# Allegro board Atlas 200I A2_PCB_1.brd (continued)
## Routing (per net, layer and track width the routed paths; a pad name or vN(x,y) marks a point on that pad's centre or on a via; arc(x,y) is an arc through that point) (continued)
$51N189030: length 32.9
  TOP w0.203: v1(83.96,69.22) 83.96,69.74 84.12,69.9 84.12,70.02 85.17,71.06 85.17,75.24 84.91,75.49 84.91,82.69 83.87,83.73 U25.3 ; R625.2 v1(96.57,62.51)
  ART04 w0.203: v1(83.96,69.22) 83.96,68.69 86.31,66.34 92.95,66.34 96.57,62.73 v1(96.57,62.51)
$51N189031: length 14.2
  TOP w0.203: U25.2 v1(81.68,83.08) ; R627.2 71.01,80.45 v1(71.02,80.46)
  ART04 w0.203: v1(81.68,83.08) 81.59,83.16 78.78,83.16 78.54,82.92 78.14,82.92 77.9,83.16 75.84,83.16 74.79,82.1 74.79,81.6 73.65,80.46 v1(71.02,80.46)
$51N193077: length 2.1
  TOP w0.203: R678.2 119.25,69.79 118.75,70.29 U21.2
$51N193392: length 2.2
  TOP w0.203: R676.2 120.11,69.8 119.4,70.5 U21.3
$51N193887: length 1.7
  TOP w0.203: R553.1 122,79.18 U21.8
$51N194066: length 1.7
  TOP w0.203: R629.1 116.3,79.18 U33.8
$51N194833: length 2.4
  TOP w0.203: U21.4 120.05,70.72 121.11,69.66 R5.2
$51N194878: length 12.3
  TOP w0.203: U21.5 120.7,72.64 119.23,74.11 111.75,74.11 110.76,73.13 R6.2
$51N196011: length 2.1
  TOP w0.203: R612.2 113.7,70.16 U33.3
$51N196013: length 1.9
  TOP w0.203: U33.2 113.05,69.7 R671.2
$51N196656: length 3
  TOP w0.203: U33.5 115,70.62 115.35,70.27 116.22,70.27 116.42,70.06 R19.2
$51N196657: length 2.3
  TOP w0.203: R7.2 114.35,70.62 U33.4
$51N198291: length 1.9
  TOP w0.203: R634.2 113.05,81.37 U34.2
$51N198558: length 2.1
  TOP w0.203: U34.3 113.7,81.83 R620.2
$51N199282: length 2.3
  TOP w0.203: U34.4 114.35,82.29 R670.2
$51N199818: length 3
  TOP w0.203: U34.5 115,82.29 115.36,81.93 116.22,81.93 116.42,81.73 R641.2
$51N202756: length 8.5
  TOP w0.203: U34.8 116.3,90.52 115.66,91.17 113.9,91.17 113.25,90.52 112.14,90.52 R239.1
$51N202938: length 2.7
  TOP w0.203: U35.8 122.01,88.29 122.27,88.03 R552.1
$51N203980: length 1.9
  TOP w0.203: U35.2 118.76,81.37 R53.2
$51N204476: length 2.1
  TOP w0.203: U35.3 119.41,81.83 R557.2
$51N204970: length 2.4
  TOP w0.203: R572.2 120.83,81.32 120.06,82.1 U35.4
$51N205764: length 3
  TOP w0.203: R556.2 122.13,81.73 121.93,81.93 121.09,81.93 120.71,82.32 U35.5
$51N207141: length 4.2
  TOP w0.203: R20.1 74.21,87.59 75.47,86.33 U25.8
$52N827: length 1.4
  TOP w0.203: R482.1 v1(114.18,102.36) 114.21,102.36 114.46,102.61 U17.6
$52N828: length 1.4
  TOP w0.203: R481.1 v1(114.18,103.38) 114.45,103.11 U17.5
$52N832: length 4.3
  TOP w0.203: 121.03,101.35 121.03,101.07 120.78,100.81 119.13,100.81 118.87,101.07 R487.1 118.62,101.35 118.35,101.61 U17.1
$52N833: length 4.3
  TOP w0.203: U17.2 118.34,102.11 118.59,102.36 R486.1 118.87,102.08 119.1,101.85 120.8,101.85 121.03,102.08 121.03,102.36
$52N834: length 4.5
  TOP w0.203: U17.3 118.11,102.61 R488.1 118.87,103.1 119.1,102.87 120.8,102.87 121.03,103.1 121.03,103.38
$52N843: length 4.9
  TOP w0.203: R489.2 98.65,115.93 98.42,115.7 95.94,115.7 95.32,116.31 U18.5
$52N844: length 2.1
  TOP w0.203: R492.1 96,116.35 v1(95.76,116.59) 95.38,116.96 U18.6
$52N845: length 2
  TOP w0.203: U18.7 95.5,117.61 v1(95.76,117.35) 95.77,117.36 R493.1
$52N846: length 4
  TOP w0.203: v1(91.69,117.35) 91.43,117.61 U18.2 88.98,117.61 88.23,116.85 R490.2
$52N847: length 5.7
  TOP w0.203: R491.2 88.62,115.96 88.82,116.17 88.82,116.74 89.05,116.96 U18.3 91.12,116.96 91.31,116.76 92.25,116.76 v1(92.84,117.35)
$52N2706: length 10.4
  TOP w0.203: R498.1 117.04,100.46 117.04,94.34 v1(116.24,93.53) 115.44,92.74 U19.23
$52N2707: length 9.3
  TOP w0.203: R499.1 116.31,100.38 v1(116.31,94.51) 115.18,93.39 U19.22
$55N3286: length 2.3
  TOP w0.203: U36.1 91.28,75.81 90.51,75.04 90.51,74.92 R459.2
$55N3381: length 2.2
  TOP w0.203: Q1.3 75.31,95.71 75.11,95.91 R549.1 C307.1
$55N3383: length 3.8
  TOP w0.203: U36.40 98.55,85.04 98.79,85.28 R550.2
$55N3386: length 10.9
  TOP w0.203: v1(65.53,94.01) R560.1 65.53,92.41 R558.2 ; v1(69.95,90.09) 70.13,89.92 C317.1 70.27,89.43 70.82,89.97 X3.1
  ART03 w0.203: v1(65.53,94.01) 66.47,94.01 69.95,90.53 v1(69.95,90.09)
$55N3387: length 4.1
  TOP w0.203: X3.3 67.98,92.86 C314.1 66.98,93.29 R560.2 66.34,92.41 R559.2
$55N29278: length 2.9
  TOP w0.203: Q6.3 105.69,87.53 106.07,87.91 R555.1 C312.1
$55N30280: length 8.1
  TOP w0.203: U36.41 98.15,84.1 98.3,83.95 99.06,83.95 99.64,84.53 104.47,84.53 104.93,84.07 R458.2
$55N32703: length 7.8
  TOP w0.203: v1(99.07,79.83) 99.08,79.82 U36.28 100.19,79.82 100.51,80.14 R649.2 ; U36.16 v1(97.75,75.15)
  ART03 w0.203: v1(97.75,75.15) 99.07,76.47 v1(99.07,79.83)
$56N3501: length 2.7
  TOP w0.203: U37.2 26.77,115.67 27.43,116.33 27.43,116.61 R562.2
$56N3504: length 2.4
  TOP w0.203: R607.2 27.98,118.24 26.68,116.94 U37.3
$56N3505: length 2.1
  TOP w0.203: U37.6 17.58,116.94 R561.1
$56N3511: length 3.2
  TOP w0.203: U37.1 27.25,114.4 28.04,115.19 R563.1
$56N3513: length 2
  TOP w0.203: U37.5 17.33,118.21 R567.2
$56N3514: length 2.2
  TOP w0.203: U37.7 17.84,115.67 R619.2
$56N3541: length 2.1
  TOP w0.203: R570.1 83.47,93.68 83.91,94.12 U38.57
$56N3566: length 2.1
  TOP w0.203: U38.23 90.69,103.84 91.03,104.19 R573.2
$56N3571: length 0.9
  TOP w0.203: R570.2 R574.1
$56N3579: length 6.8
  TOP w0.203: C343.1 85.47,89.56 85.15,89.88 X4.1 84.75,90.13 83.69,91.19 81.84,91.19 81.69,91.34 R578.1 81.69,92.66 81.75,92.73 R580.2
$56N3581: length 6.1
  TOP w0.203: R579.2 80.9,92.58 80.87,92.56 R578.2 80.87,88.95 81.08,88.75 C344.1 81.56,88.75 81.88,88.43 X4.3
$56N19655: length 1.2
  TOP w0.203: U38.27 89.09,103.09 89.38,103.38 R651.2
$56N19722: length 1.1
  TOP w0.203: R652.1 82.92,100.97 U38.41

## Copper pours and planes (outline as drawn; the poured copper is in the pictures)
3V3_USB30_SW on ART03 (solid shape): 108.57,16.23 111.56,16.23 111.82,15.96 111.82,15.24 111.54,14.96 106.45,14.96 106.1,14.61 103.76,14.61 103.71,14.66 103.71,15.25 103.72,15.29 103.74,15.33 103.8,15.33 103.85,15.34 103.9,15.35 103.94,15.37 104.14,15.37 104.14,15.31 104.15,15.26 104.16,15.21 104.19,15.16 104.22,15.12 104.25,15.08 104.29,15.05 104.34,15.02 104.39,15 104.44,14.99 104.5,14.98 104.55,14.99 104.6,15 104.65,15.02 104.7,15.05 104.74,15.08 104.77,15.12 104.8,15.16 104.83,15.21 104.84,15.26 104.85,15.31 104.85,15.37 104.84,15.42 104.83,15.47 104.8,15.52 104.77,15.56 104.74,15.6 104.7,15.64 104.65,15.66 104.6,15.68 104.55,15.69 104.5,15.7 104.44,15.69 104.39,15.68 104.34,15.66 104.29,15.64 104.25,15.6 104.22,15.56 104.19,15.52 104.16,15.47 104.15,15.42 104.14,15.37 103.94,15.37 103.95,15.37 104,15.4 104.04,15.44 104.07,15.48 104.1,15.53 104.13,15.58 104.14,15.63 104.15,15.68 104.15,15.74 104.14,15.79 104.12,15.85 104.1,15.9 104.07,15.94 104.03,15.98 104.01,16 104.62,16.61 108.18,16.61
12V_FAN on TOP (solid shape): 117.66,111.95 117.66,110.25 117.52,110.1 117.5,110.1 117.5,107.91 117.09,107.5 115.3,107.5 115.04,107.77 115.04,107.91 115.66,107.91 115.66,108.18 115.29,108.18 115.29,107.91 115.04,107.91 115.04,108.8 115.06,108.8 115.06,109.57 115.61,109.57 115.61,109.83 115.06,109.83 115.06,110.06 115.61,110.06 115.61,110.34 115.06,110.34 115.06,110.57 115.61,110.57 115.61,110.83 115.06,110.83 115.06,111.07 115.61,111.07 115.61,111.33 115.06,111.33 115.06,111.99 115.33,112.25 117.36,112.25
AGND_AUDIO on TOP (solid shape): 102.75,53.76 102.76,53.67 102.82,53.58 103.22,53.18 103.22,53.17 103.24,53.08 103.28,53 103.28,51.96 103.28,51.93 103.28,51.43 102.9,51.05 102.84,50.95 102.81,50.85 102.81,50.45 102.84,50.34 102.9,50.25 102.97,50.18 102.97,49.74 102.45,49.74 102.4,49.7 102.4,47.88 102.37,47.85 102.14,47.85 102.1,47.89 102.1,49.7 102.06,49.74 101.03,49.74 101.03,49.91 101.04,49.93 101.09,50.02 101.11,50.13 101.06,50.32 100.92,50.45 100.89,50.46 100.89,54.28 100.97,54.28 100.98,54.27 101.09,54.2 101.22,54.18 101.47,54.28 101.58,54.53 101.57,54.6 101.55,54.67 101.56,54.77 101.64,54.81 102.75,54.81
AGND_AUDIO on TOP (solid shape): 102.51,47.43 102.53,47.4 103.16,46.78 103.16,46.76 103.29,46.58 103.5,46.51 103.76,46.61 103.86,46.86 103.79,47.08 103.6,47.21 103.59,47.21 103.48,47.32 103.45,47.44 103.55,47.5 104.11,47.5 104.24,47.37 104.24,46.28 104.01,46.05 100.43,46.05 100.3,46.18 100.3,46.63 100.47,46.8 100.49,46.83 100.51,46.86 100.57,46.88 100.61,46.84 100.72,46.6 100.97,46.51 101.16,46.56 101.29,46.71 101.29,46.72 101.34,46.77 101.42,46.8 101.49,46.76 101.53,46.71 101.66,46.56 101.85,46.51 102.11,46.61 102.21,46.86 102.18,47.01 102.08,47.14 102.08,47.5 102.47,47.5
AGND_AUDIO on TOP (solid shape): outline of 172 points within 128.7,34.73 134.34,42.21
AGND_MIC on TOP (solid shape): outline of 120 points within 129.18,35.72 130.98,37.53
GND on TOP (solid shape): 13.06,103.84 13.06,102.31 12.95,102.21 11.96,102.21 11.89,102.29 11.89,103.89 11.94,103.94 12.95,103.94
GND on TOP (solid shape): 17.25,60.91 17.25,57.35 16.94,57.05 15.21,57.05 14.94,57.33 14.94,61.19 15.19,61.44 16.71,61.44
GND on TOP (solid shape): 94.95,31.37 94.95,28.47 94.82,28.35 93.37,28.35 93.24,28.47 93.24,31.37 93.37,31.5 94.82,31.5
GND on TOP (solid shape): 112.17,26.42 112.17,25.23 112.09,25.16 110.25,25.16 110.11,25.3 110.11,26.21 110.54,26.64 111.94,26.64
GND on TOP (solid shape): 123.24,45.03 123.24,43.99 123.15,43.9 119.95,43.9 119.86,43.99 119.86,45.03 119.93,45.1 123.18,45.1
GND on TOP (solid shape): 8.92,15.11 8.9,15.1 8.9,14.44 8.64,14.17 6.43,14.17 5.99,14.61 5.99,16.2 6.07,16.28 8.92,16.28
GND on TOP (solid shape): 88.65,31.37 88.65,28.5 88.54,28.4 87.33,28.4 86.96,28.77 86.96,31.3 87.15,31.5 88.52,31.5
GND on TOP (solid shape): 125.76,22.4 125.76,19.41 125.55,19.2 121.44,19.2 120.12,17.88 118.34,17.88 118.31,17.91 118.31,18.59 118.57,18.85 118.57,22.07 119.23,22.73 125.43,22.73
GND on TOP (solid shape): 71.55,27.3 71.55,25.31 71.22,24.98 71.22,21.69 71.04,21.51 69.19,21.51 68.71,22 68.71,25.25 69.06,25.6 69.9,25.6 70.33,26.04 70.33,27.18 70.59,27.43 71.42,27.43
GND on TOP (solid shape): 101.83,36.8 101.83,35.31 101.22,34.7 101.22,30.86 100.84,30.48 100.03,30.48 99.77,30.73 99.77,32.77 99.06,33.48 99.06,35.92 99.35,36.21 99.35,36.89 99.49,37.03 101.6,37.03
GND on TOP (solid shape): 122.81,111.91 122.81,109.73 123.09,109.45 123.67,109.45 123.77,109.35 123.77,107.87 123.65,107.75 122.99,107.75 122.76,107.98 122.05,107.98 121.95,108.08 121.95,111.94 122.15,112.14 122.58,112.14
GND on TOP (solid shape): 36.68,118.31 36.68,117.47 36.47,117.27 33.05,117.27 32.89,117.42 32.89,117.58 33.58,117.58 33.58,117.96 33.25,117.96 33.25,117.58 32.89,117.58 32.89,118.39 33.07,118.57 36.42,118.57
GND on TOP (solid shape): 2.83,50.2 2.93,50.14 3.05,50.11 3.96,50.11 4.01,50.06 4.01,48.67 3.94,48.59 0.91,48.59 0.53,48.97 0.53,50.47 0.76,50.7 2.34,50.7
GND on TOP (solid shape): 1,18.53 4.52,18.53 4.52,17.5 4.22,17.2 3.23,17.2 2.76,16.73 2.76,15.1 2.62,14.96 1.42,14.96 1.07,14.61 0.64,14.61 0.51,14.73 0.51,18.9 0.81,19.2 1,19.2
GND on TOP (solid shape): 4.29,90.35 4.29,89.61 3,88.32 3,87.27 2.31,86.59 0.81,86.59 0.56,86.84 0.56,90.3 0.62,90.36 1.91,90.36 1.91,89.76 2.71,89.76 2.71,90.36 3.38,90.36 3.38,90.91 3.73,90.91
GND on TOP (solid shape): 46.51,119.2 46.51,118.01 46.28,117.78 43.21,117.78 42.93,118.06 42.93,118.36 42.98,118.54 42.93,118.73 42.93,119.33 43.09,119.49 46.22,119.49
GND on TOP (solid shape): 6.17,54.76 6.17,53.36 6.13,53.33 5.93,53.13 5.52,53.13 5.28,53.37 5.28,53.59 5.22,53.65 5.17,53.7 4.84,53.7 4.77,53.77 4.77,54.79 4.79,54.81 6.12,54.81
GND on TOP (solid shape): 24.21,79.78 24.21,79.12 24.51,78.82 24.51,77.09 24.26,76.83 22.38,76.83 22.38,77.14 22.05,77.14 22.05,77.39 22.67,77.39 22.67,79.1 22.3,79.1 22.3,77.39 22.05,77.39 22.05,79.45 22.45,79.86 24.13,79.86
GND on TOP (solid shape): 55.68,13.79 55.68,2.01 54.74,1.07 54.31,1.07 54.12,1.12 53.94,1.07 53.34,1.07 53.09,1.32 53.09,11.53 52.5,12.12 50.75,12.12 50.11,12.75 50.11,14.12 50.44,14.45 55.02,14.45
GND on TOP (solid shape): 80.88,22.8 81.05,22.8 81.28,22.56 81.28,22.35 81.1,22.17 79.76,22.17 79.53,21.95 79.53,21.59 79.38,21.44 78.89,21.44 78.77,21.56 78.77,22 78.64,22.12 78.64,22.76 78.71,22.83 79.73,22.83 79.89,22.99 80.69,22.99
GND on TOP (solid shape): 48.46,36.2 48.46,34.21 48.01,33.76 47.19,33.76 46.94,33.5 46.94,33.05 47.14,32.84 47.57,32.84 47.65,32.77 47.65,31.95 47.6,31.9 46,31.9 45.92,31.98 45.92,32.74 46,32.82 46.53,32.82 46.63,32.92 46.63,33.76 47.09,34.21 47.09,36.37 47.22,36.5 48.16,36.5
GND on TOP (solid shape): 59.59,21.64 59.59,19.66 59.13,19.2 58.31,19.2 58.06,18.96 58.06,18.49 58.27,18.29 58.7,18.29 58.78,18.21 58.78,17.4 58.72,17.35 57.12,17.35 57.05,17.42 57.05,18.19 57.12,18.26 57.66,18.26 57.76,18.36 57.76,19.2 58.22,19.66 58.22,21.82 58.34,21.95 59.28,21.95
GND on TOP (solid shape): 50.27,22.62 53.37,22.62 53.42,22.61 53.47,22.61 54.39,22.61 54.51,22.62 54.61,22.67 54.62,22.68 54.76,22.68 55.22,22.23 55.22,20.85 54.97,20.6 49.02,20.6 48.77,20.85 48.77,22.23 49.38,22.84 50.06,22.84
GND on TOP (solid shape): 66.95,27.46 66.95,26.11 66.83,25.98 66.09,25.98 65.91,26.16 66.57,26.16 66.57,26.47 66.22,26.47 66.22,26.16 65.91,26.16 65.63,26.44 65.63,27.08 66.6,27.08 66.6,27.36 66.22,27.36 66.22,27.08 65.63,27.08 65.63,27.41 65.91,27.69 66.73,27.69
GND on TOP (solid shape): 110.01,34.06 110.67,34.06 111.02,33.71 111.02,32.77 110.67,32.41 110.07,32.41 110.07,32.46 109.15,32.46 109.09,32.52 109.09,32.64 109.55,32.64 109.55,33.05 109.25,33.05 109.25,32.64 109.09,32.64 109.09,32.8 108.8,32.8 108.64,32.97 105.71,32.97 105.59,33.1 105.59,34.29 105.94,34.65 109.42,34.65
GND on TOP (solid shape): 25.08,54.14 25.07,54.12 25.07,48.82 24.84,48.59 22.24,48.59 21.97,48.72 21.7,48.59 21.54,48.59 20.85,49.28 20.85,51.46 21.97,52.58 21.97,53.85 22.33,54.2 25.02,54.2
GND on TOP (solid shape): 112.85,91.36 112.85,90.93 112.75,90.83 111.92,90.83 111.46,90.37 109.46,90.37 109.35,90.48 109.35,90.73 109.96,90.73 109.96,90.75 111.05,90.75 111.05,91.13 110.76,91.13 110.76,90.75 109.96,90.75 109.96,91.14 109.66,91.14 109.66,90.73 109.35,90.73 109.35,91.36 109.46,91.47 111.39,91.47 111.41,91.49 112.73,91.49
GND on TOP (solid shape): 9.91,67.21 9.91,65.86 9.8,65.76 9.19,65.76 9.17,65.74 8.96,65.74 8.96,65.76 8.09,65.76 8.09,65.74 7.92,65.74 7.8,65.86 7.8,66.11 7.81,66.13 7.83,66.19 7.85,66.24 8.69,66.24 8.69,66.6 8.36,66.6 8.36,66.24 7.85,66.24 7.85,66.29 7.85,66.35 7.83,66.4 7.81,66.45 7.8,66.48 7.8,67.18 8.05,67.44 9.68,67.44
GND on TOP (solid shape): 23.75,82.55 25.96,82.55 25.98,82.52 25.98,81.61 25.88,81.5 22.38,81.5 22.38,82.33 22.63,82.18 22.93,82.13 23.35,82.24 23.65,82.56 23.65,82.56 23.7,82.6
GND on TOP (solid shape): 74.12,22.07 74.12,21.77 74.6,21.29 74.6,20.23 74.31,19.93 74.04,19.93 73.63,19.52 73.6,19.52 73.6,18 73.5,17.89 73.09,17.89 73.06,17.92 73.06,18.58 73.01,18.58 73.01,18.97 73.07,19.1 73.09,19.25 73.09,19.57 73.49,19.97 73.49,21.11 73.28,21.11 73.28,21.95 73.51,22.17 74.02,22.17
GND on TOP (solid shape): 101.02,14.81 101.02,13.31 100.78,13.08 100.51,13.08 100.38,12.95 100.22,12.95 100.22,12.8 100.1,12.67 100.1,12.12 99.77,11.79 99.14,11.79 99.11,11.81 99.11,12.29 99.12,12.31 99.12,12.53 99.96,13.38 99.96,13.41 100.69,13.41 100.69,13.68 100.28,13.68 100.28,13.41 99.96,13.41 99.96,14.18 99.69,14.45 99.21,14.45 99.09,14.58 99.09,14.99 99.16,15.06 100.76,15.06
GND on TOP (solid shape): 59.11,42.49 59.11,41.27 58.85,41.02 58.85,40.31 58.83,40.29 58.83,39.11 58.55,39.11 58.55,38.84 58.39,38.84 58.29,38.94 58.29,39.62 58.67,39.62 58.67,40.03 58.42,40.03 58.42,39.62 58.29,39.62 58.29,40.56 58.7,40.56 58.7,40.94 58.45,40.94 58.45,40.56 58.29,40.56 58.29,41.36 58.42,41.49 58.42,42.49 58.52,42.6 59,42.6
GND on TOP (solid shape): 89.43,109.22 89.43,108.28 88.72,107.57 87.81,107.57 87.43,107.19 85.52,107.19 85.37,107.34 85.37,107.9 88.65,107.9 88.65,108.36 88.34,108.36 88.34,107.9 85.37,107.9 85.37,108.84 88.24,108.84 88.24,109.27 87.96,109.27 87.96,108.84 85.37,108.84 85.37,108.86 86.08,109.58 89.08,109.58
GND on TOP (solid shape): 101.45,19.18 101.45,17.88 101.12,17.55 100.25,17.55 99.85,17.14 99.39,17.14 99.31,17.22 99.31,17.5 99.72,17.5 99.72,17.87 100.86,17.87 100.86,18.31 100.56,18.31 100.56,17.87 99.72,17.87 99.72,17.93 99.44,17.93 99.44,17.5 99.31,17.5 99.31,18.54 100.1,18.54 100.1,18.8 99.69,18.8 99.69,18.54 99.31,18.54 99.31,19.28 99.57,19.53 101.09,19.53
GND on TOP (solid shape): 7.31,64.08 7.33,64.07 7.37,64.05 7.42,64.04 7.47,64.03 7.52,64.03 7.56,64.04 7.6,64.05 7.66,64.07 7.79,63.93 7.79,63.14 7.82,63.14 7.82,62.99 7.79,62.99 7.79,62.33 7.74,62.28 6.35,62.28 6.17,62.46 7.34,62.46 7.34,62.69 6.93,62.69 6.93,62.46 6.17,62.46 6.1,62.53 6.1,63.45 7.37,63.45 7.37,63.73 6.96,63.73 6.96,63.45 6.1,63.45 6.1,63.55 6.63,64.08
GND on TOP (solid shape): 55.52,44.73 55.52,43.84 55.8,43.56 57.02,43.56 57.1,43.48 57.1,42.95 57.07,42.93 54.84,42.93 54.69,43.08 56.74,43.08 56.74,43.36 56.31,43.36 56.31,43.08 54.69,43.08 54.66,43.1 55.8,43.1 55.8,43.36 55.4,43.36 55.4,43.1 54.66,43.1 54.66,43.23 55.12,43.23 55.12,43.66 54.84,43.66 54.84,43.23 54.66,43.23 54.66,43.33 54.46,43.54 54.39,43.54 54.24,43.69 54.24,44.84 54.33,44.93 55.32,44.93
GND on TOP (solid shape): 122.35,25.86 122.35,25.68 122.4,25.63 122.4,25.57 122.46,25.57 122.56,25.48 122.91,25.48 123.29,25.1 123.29,23.32 123.14,23.16 119.81,23.16 119.53,23.44 119.53,24.4 122.18,24.4 122.18,24.77 120.59,24.77 120.59,24.4 119.53,24.4 119.53,25.02 122.2,25.02 122.2,25.3 120.6,25.3 120.6,25.02 119.53,25.02 119.53,25.5 122.2,25.5 122.2,25.78 120.6,25.78 120.6,25.5 119.53,25.5 119.53,25.68 119.87,26.02 122.19,26.02
GND on TOP (solid shape): 60.27,92.43 60.27,91.77 59.95,91.45 59.85,91.4 59.65,91.29 59.46,91.19 59.28,91.07 59.1,90.95 58.92,90.82 58.75,90.68 58.58,90.54 58.42,90.4 58.34,90.32 56.26,90.32 56.08,90.5 56.08,90.58 56.13,90.58 56.13,91.39 56.44,91.69 57.78,91.69 57.86,91.77 58.93,91.77 58.93,91.87 59.94,91.87 59.94,92.35 59.64,92.35 59.64,91.87 58.93,91.87 58.93,92.25 58.65,92.25 58.65,91.77 57.86,91.77 58.62,92.53 60.17,92.53
GND on TOP (solid shape): 111.91,44.35 111.91,43.23 112.31,42.83 112.31,40.8 111.99,40.48 111.99,39.17 111.84,39.01 110.16,39.01 109.98,39.19 109.98,41.05 112.02,41.05 112.02,41.3 111.67,41.3 111.67,41.05 109.98,41.05 109.98,41.09 109.99,41.12 110,41.18 110.01,41.25 110.01,41.31 110,41.37 109.99,41.44 109.98,41.47 109.98,42.39 109.97,42.4 111.97,42.4 111.97,42.7 111.56,42.7 111.56,42.4 109.97,42.4 109.6,42.77 108.92,42.77 108.66,43.03 108.66,43.61 109.07,44.02 109.91,44.02 110.41,44.53 111.73,44.53
GND on TOP (solid shape): 95.55,37.31 95.55,35.13 95.22,34.8 90.8,34.8 90.19,35.41 90.18,35.42 90.11,35.48 89.17,35.48 89.07,35.38 89.07,34.65 89.02,34.59 87.04,34.59 87.01,34.62 87.01,35.36 86.89,35.48 86.1,35.48 86.05,35.53 86.05,35.69 86.1,35.74 86.89,35.74 86.99,35.84 86.99,36.6 87.04,36.65 89.1,36.65 89.17,36.58 89.17,35.84 89.27,35.74 90.11,35.74 90.18,35.81 90.19,35.82 90.82,36.45 91.29,36.45 91.29,36.91 91.03,36.91 91.03,36.45 90.82,36.45 90.82,37.03 90.96,37.16 91.81,37.16 92.04,37.39 95.47,37.39
GND on TOP (solid shape): 42.65,43.94 42.33,43.94 42.33,42.52 41.55,41.73 40.03,41.73 39.95,41.66 35.74,41.66 35.68,41.71 35.64,41.74 35.6,41.76 35.56,41.78 35.51,41.78 35.48,41.78 34.67,41.78 34.67,41.91 32.99,41.91 32.99,41.81 32.97,41.79 32.92,41.78 32.87,41.77 32.82,41.74 32.77,41.71 32.72,41.66 32.31,41.66 32.18,41.78 32.18,42.85 32.59,42.85 32.59,43.26 32.31,43.26 32.31,42.85 32.18,42.85 32.18,43.44 33.08,43.44 33.08,43.71 36.14,43.71 36.32,43.54 41.45,43.54 41.65,43.73 41.89,43.73 41.89,43.97 42.01,44.09 42.65,44.09
GND on TOP (solid shape): 2.05,103.4 2.26,103.34 2.47,103.4 3.73,103.4 3.94,103.34 4.15,103.4 5.71,103.4 5.92,103.34 6.13,103.4 7.49,103.4 7.7,103.34 7.91,103.4 7.92,103.4 8.13,103.2 8.13,102.48 7.98,102.33 7.98,102.18 7.87,102.08 0.91,102.08 0.58,102.41 0.58,103.23 0.76,103.4
GND on TOP (solid shape): 53.06,117.08 53.06,115.94 52.96,115.85 51.97,115.85 51.71,115.6 51.18,115.6 51,115.42 51,114.76 50.92,114.67 49.71,114.67 49.32,114.29 49.32,113.86 49.23,113.77 44.88,113.77 44.65,114 44.65,114.07 45.42,114.07 45.42,114.3 44.96,114.3 44.96,114.07 44.65,114.07 44.65,114.78 44.78,114.91 50.72,114.91 50.72,115.19 50.34,115.19 50.34,114.91 44.78,114.91 45.57,115.7 46.23,115.7 46.38,115.85 47.52,115.85 47.52,116.31 47.22,116.31 47.22,115.85 46.38,115.85 47.12,116.59 48.29,116.59 48.74,117.04 52.04,117.04 52.16,117.15 52.98,117.15
GND on TOP (solid shape): 106.55,107.95 106.55,106.43 103.38,103.25 101.22,103.25 100.46,102.49 100.46,98.61 100.43,98.58 100.43,95.98 100.33,95.89 100.33,95.25 98.93,95.25 98.81,95.38 98.81,97.28 98.73,97.36 98.73,100.31 98.6,100.44 98.6,100.79 98.7,100.79 98.7,101.04 99.59,101.04 99.59,101.35 99.11,101.35 99.11,101.04 98.7,101.04 98.7,101.65 98.6,101.65 98.6,101.96 98.73,102.08 98.73,102.39 99.47,102.39 99.47,102.64 99.03,102.64 99.03,102.39 98.73,102.39 98.73,103.4 99.39,103.4 99.39,103.68 99.01,103.68 99.01,103.4 98.73,103.4 98.73,104.39 99.36,104.39 99.36,104.65 98.98,104.65 98.98,104.39 98.73,104.39 98.73,105.84 99.95,107.06 100.01,107.11 100.12,107.19 100.22,107.28 100.32,107.38 100.41,107.48 100.49,107.59 100.54,107.65 102.11,109.22 105.28,109.22
GND on TOP (solid shape): 1.93,83.69 1.97,83.69 2,83.67 2.01,83.65 2.03,83.63 2.03,83.6 2.03,83.57 1.99,83.5 1.95,83.42 1.92,83.34 1.89,83.26 1.87,83.17 1.85,83.08 1.85,83 1.85,82.9 1.85,82.81 1.87,82.72 1.89,82.63 1.93,82.54 1.97,82.45 2.01,82.37 2.07,82.29 2.13,82.22 2.2,82.15 2.27,82.09 2.34,82.04 2.43,81.99 2.51,81.95 2.6,81.92 2.69,81.9 2.78,81.88 2.88,81.87 2.97,81.87 3.06,81.88 3.14,81.89 3.23,81.91 3.31,81.94 3.39,81.97 3.46,82.02 3.54,82.05 3.57,82.05 3.59,82.05 3.62,82.03 3.64,82.02 3.65,81.99 3.66,81.95 3.66,80.62 3.18,80.14 3.18,77.1 3.07,76.99 1.68,76.99 0.51,78.16 0.51,82.96 1.19,82.96 1.19,83.41 0.89,83.41 0.89,82.96 0.51,82.96 0.51,83.41 0.79,83.69
GND on TOP (solid shape): 31.65,45.62 31.65,45.29 31.57,45.21 31.57,41.53 32.15,40.95 32.15,40.21 32.31,40.06 33.13,40.06 33.32,39.86 33.32,37.54 32.71,36.93 31.36,36.93 30.94,37.36 30.94,39.37 32.98,39.37 32.98,39.76 32.69,39.76 32.69,39.37 30.94,39.37 30.94,39.52 31.75,39.52 31.75,39.88 31.29,39.88 31.29,39.52 30.94,39.52 30.94,40.51 31.75,40.51 31.75,40.79 31.27,40.79 31.27,40.51 30.94,40.51 30.94,41.12 31.39,41.12 31.39,41.51 31.11,41.51 31.11,41.12 30.94,41.12 30.94,42.06 31.39,42.06 31.39,42.42 31.17,42.42 31.17,42.06 30.94,42.06 30.94,42.98 31.39,42.98 31.39,43.38 31.14,43.38 31.14,42.98 30.94,42.98 30.94,43.92 31.39,43.92 31.39,44.35 31.14,44.35 31.14,43.92 30.94,43.92 30.94,44.91 31.42,44.91 31.42,45.42 31.17,45.42 31.17,44.91 30.94,44.91 30.94,45.62 31.04,45.72 31.55,45.72
GND on TOP (solid shape): 81.38,28.02 81.38,26.75 81.84,26.29 81.84,25.73 82.07,25.5 82.64,25.5 82.64,27.45 82.67,27.49 83,27.49 83.01,27.48 83.01,26.86 82.89,26.74 82.89,25.82 82.96,25.75 83.09,25.75 83.13,25.8 83.13,26.4 83.37,26.4 83.38,26.38 83.38,25.48 83.97,25.48 84.02,25.43 84.02,23.5 83.97,23.44 83.39,23.44 83.38,23.44 83.38,22.55 83.14,22.55 83.13,22.56 83.13,23.1 83.12,23.11 82.89,23.11 82.89,22.55 82.87,22.53 82.65,22.53 82.64,22.55 82.64,23.38 82.6,23.42 82.07,23.42 82.07,24.7 81.86,24.91 81.86,25.29 81.7,25.29 81.64,25.35 81.05,25.35 81.05,25.8 81,25.85 81,26.05 80.8,26.05 80.58,26.26 77.55,26.26 77.24,26.57 77.23,26.57 77.03,26.77 75.85,26.77 74.79,25.7 71.98,25.7 71.7,25.98 71.7,27.48 72.11,27.89 74.2,27.89 75.32,27.43 75.34,27.41 78.74,27.41 79.25,27.91 80.31,27.91 80.59,28.19 81.2,28.19
GND on TOP (solid shape): 10.32,43.65 10.38,43.63 10.43,43.62 10.49,43.62 10.54,43.63 10.6,43.65 10.63,43.66 11.64,43.66 11.66,43.65 11.71,43.62 11.77,43.6 11.83,43.59 11.91,43.59 12.12,43.38 12.12,39.52 11.91,39.32 11.48,39.32 11.23,39.57 11.23,39.83 11.71,39.83 11.71,40.28 11.46,40.28 11.46,39.83 11.23,39.83 11.23,41.05 11.73,41.05 11.73,41.45 11.46,41.45 11.46,41.05 11.23,41.05 11.23,42.29 11.05,42.47 11.05,42.49 11.02,42.49 10.97,42.55 8.2,42.55 7.9,42.24 7.9,39.52 7.75,39.37 6.68,39.37 6.6,39.45 6.6,39.67 7.52,39.67 7.52,39.98 7.16,39.98 7.16,39.67 6.6,39.67 6.6,40.79 7.52,40.79 7.52,41.1 7.16,41.1 7.16,40.79 6.6,40.79 6.6,42.95 10.74,42.95 10.74,43.36 10.49,43.36 10.49,42.95 9.78,42.95 9.78,43.38 9.47,43.38 9.47,42.95 8.79,42.95 8.79,43.38 8.51,43.38 8.51,42.95 6.6,42.95 6.6,43.03 7.24,43.66 10.29,43.66
GND on TOP (solid shape): 31.65,57.53 31.65,55.29 31.75,55.19 31.75,52.95 31.73,52.93 31.7,52.89 31.68,52.84 31.67,52.79 31.67,52.77 31.67,52.39 31.67,52.36 31.68,52.31 31.7,52.27 31.73,52.23 31.78,52.18 31.78,51.46 31.91,51.32 31.91,51.29 31.91,51.26 31.91,51.24 31.89,51.21 31.84,51.18 31.8,51.15 31.76,51.11 31.72,51.07 31.7,51.03 31.68,50.98 31.66,50.93 31.66,50.88 31.66,50.82 31.66,50.77 31.68,50.72 31.7,50.67 31.73,50.62 31.77,50.58 31.81,50.55 31.85,50.52 31.9,50.49 31.97,50.47 31.97,49.82 31.9,49.76 31.9,47.9 31.88,47.88 31.6,47.88 31.6,49.78 31.39,49.78 31.39,47.88 31.11,47.88 31.11,49.78 30.89,49.78 30.89,47.88 30.68,47.88 30.61,47.96 30.61,49.78 30.6,49.79 30.56,49.83 30.35,49.83 30.3,49.89 30.3,51 30.35,51.05 30.35,55.14 31.37,55.14 31.37,57.28 31.14,57.28 31.14,55.14 30.86,55.14 30.86,57.28 30.63,57.28 30.63,55.14 30.35,55.14 30.35,55.23 30.36,55.23 30.36,57.41 30.35,57.41 30.35,57.58 30.38,57.61 31.57,57.61
GND on TOP (solid shape): outline of 81 points within 1.78,50.72 6.45,57.25
GND on TOP (solid shape): outline of 98 points within 78.87,87.35 81.81,101.09
GND on TOP (solid shape): 111.48,19.1 111.48,17.67 111.32,17.51 110.63,17.51 110.54,17.61 110.54,18.18 110.54,18.21 110.36,18.64 109.93,18.81 109.72,18.77 109.54,18.66 109.52,18.65 109.42,18.65 109.4,18.66 109.22,18.77 109.01,18.81 108.76,18.76 108.55,18.6 108.48,18.53 108.48,18.51 108.48,18.5 108.42,18.36 108.41,18.21 108.41,18.16 108.42,18.1 108.42,17.6 108.34,17.52 107.91,17.52 107.79,17.63 107.79,18.18 107.79,18.21 107.62,18.64 107.19,18.81 106.98,18.77 106.79,18.66 106.78,18.65 106.68,18.65 106.66,18.66 106.48,18.77 106.26,18.81 105.84,18.64 105.66,18.21 105.67,18.16 105.67,18.1 105.67,17.58 105.63,17.53 105.04,17.53 104.86,17.71 104.86,18.83 104.86,18.83 104.86,19.04 105.03,19.2 111.38,19.2
GND on TOP (solid shape): outline of 126 points within 68.28,110.55 81.51,117.16
GND on TOP (solid shape): outline of 162 points within 48.59,29.68 54.58,36.07
GND on TOP (solid shape): outline of 216 points within 65.25,111.2 86.87,119.46
GND on BOTTOM (solid shape): 47.61,31.92 45.96,31.92 45.96,32.8 47.61,32.8
GND on BOTTOM (solid shape): 58.7,17.39 57.16,17.39 57.16,18.21 58.7,18.21
GND on BOTTOM (solid shape): 63.04,113.67 59.39,113.67 59.39,117.17 63.04,117.17
GND on BOTTOM (solid shape): 83.92,23.56 82.07,23.56 82.07,25.4 83.92,25.4
GND on BOTTOM (solid shape): 88.98,34.7 87.13,34.7 87.13,36.52 88.98,36.52
GND on BOTTOM (solid shape): 109.71,13.6 106.65,13.6 106.65,14.66 109.71,14.66
GND on BOTTOM (solid shape): 116.76,101.72 115.73,101.72 115.73,102.96 116.76,102.96
GND on BOTTOM (solid shape): 54.58,0.53 54.56,0.51 48.56,0.51 48.56,1.02 54.58,1.02
GND on BOTTOM (solid shape): 13.64,55.42 13.64,51.86 9.93,51.86 9.78,52.01 9.78,55.35 10.01,55.58 13.48,55.58
GND on BOTTOM (solid shape): 59.92,35.64 59.92,32.56 59.66,32.31 56.29,32.31 56.03,32.56 56.03,35.64 56.29,35.89 59.66,35.89
GND on ART03 (solid shape): 69.08,45.59 67.69,45.59 67.69,50.55 69.08,50.55
GND on ART03 (solid shape): 72.52,46.99 70.81,46.99 70.81,50.55 72.52,50.55
GND on ART03 (solid shape): 76.82,54.23 73.21,54.23 73.21,57.91 76.82,57.91
GND on ART03 (solid shape): 72.25,54.23 70.63,54.23 70.4,54.46 70.4,57.85 70.46,57.91 72.25,57.91
GND on ART03 (solid shape): 46.94,50.24 46.94,47.19 46.81,47.07 40.61,47.07 40.51,47.17 40.51,50.37 46.81,50.37
GND on ART03 (solid shape): 88.83,57.7 88.83,54.18 88.83,54.14 88.77,54.08 82.27,54.08 82.26,54.09 82.26,57.74 82.27,57.76 88.77,57.76
GND on ART03 (solid shape): 90.54,50.53 90.58,50.44 90.65,50.37 90.65,47.17 90.53,47.04 82.51,47.04 82.51,50.55 90.53,50.55
GND on ART03 (solid shape): 111.4,12.09 111.4,9.09 111.33,9.02 105.64,9.02 105.03,9.63 105.03,10.95 105.54,11.46 105.54,11.96 105.77,12.19 111.3,12.19
GND on ART03 (solid shape): 75.1,50.55 75.17,50.52 75.25,50.51 75.33,50.52 75.4,50.55 77.05,50.55 77.05,46.99 73.48,46.99 73.48,50.55
GND on ART03 (solid shape): 39.65,27.58 39.65,27.13 39.75,27.03 39.75,24.95 40.45,24.25 40.49,24.25 40.56,24.18 44.2,24.18 44.31,24.07 44.31,22.8 44.04,22.53 36.5,22.53 35.79,23.25 35.79,27.47 35.92,27.6 39.63,27.6
GND on ART03 (solid shape): 42.79,28.69 42.79,28.12 42.97,27.94 42.97,27.48 43.48,26.97 44.6,26.97 44.64,26.94 44.64,25.3 40.85,25.3 40.61,25.54 40.61,27.48 40.95,27.82 42.09,27.82 42.44,28.17 42.44,28.66 42.51,28.73 42.75,28.73
GND on ART03 (solid shape): 92.19,14.24 92.19,12.17 92.13,11.98 92.19,11.79 92.19,8.68 91.86,8.36 86.22,8.36 86.11,8.47 86.11,11.79 86.26,11.93 86.26,13.6 86.26,13.6 86.26,14.25 86.39,14.38 92.05,14.38
GND on ART03 (solid shape): 35.13,50.37 35.24,50.11 35.51,50 35.77,50.11 35.89,50.37 39.45,50.37 39.45,47.07 31.9,47.07 31.57,47.4 31.57,50.37
GND on ART03 (solid shape): 97.68,57.67 97.68,54.14 97.66,54.13 95.94,54.13 95.83,54.18 95.71,54.2 94.79,54.2 94.67,54.18 94.56,54.13 92.94,54.13 92.83,54.18 92.71,54.2 91.79,54.2 91.67,54.18 91.56,54.13 91.35,54.13 91.35,57.68 97.66,57.68
GND on ART03 (solid shape): 69.08,59.34 69.08,58.77 68.83,58.53 68.83,54.03 68.1,54.03 67.87,54.25 67.84,54.3 67.84,54.36 67.85,54.41 67.85,54.46 67.5,54.81 67.14,54.46 67.14,54.41 67.15,54.36 67.14,54.27 67.06,54.23 67.03,54.23 65.97,55.29 65.97,58.89 66.45,59.36 69.06,59.36
GND on ART03 (solid shape): 74.4,16 74.4,9.71 72.58,7.9 72.58,2.65 71.95,2.02 62.82,2.02 62.81,2.03 61.02,2.03 60.09,2.96 60.09,12.18 61.82,13.92 61.87,13.92 61.92,13.93 61.97,13.95 62.02,13.98 62.06,14.01 62.1,14.05 62.13,14.09 62.15,14.14 62.17,14.19 62.18,14.25 62.51,14.25 62.51,14.2 62.52,14.14 62.53,14.09 62.56,14.05 62.59,14 62.62,13.96 62.66,13.93 62.71,13.9 62.76,13.88 62.81,13.87 62.87,13.87 62.92,13.87 62.97,13.88 63.02,13.9 63.07,13.93 63.11,13.96 63.14,14 63.17,14.05 63.2,14.09 63.21,14.14 63.22,14.2 63.22,14.25 63.21,14.3 63.2,14.35 63.17,14.4 63.14,14.45 63.11,14.49 63.07,14.52 63.02,14.55 62.97,14.57 62.92,14.58 62.87,14.58 62.81,14.58 62.76,14.57 62.71,14.55 62.66,14.52 62.62,14.49 62.59,14.45 62.56,14.4 62.53,14.35 62.52,14.3 62.51,14.25 62.18,14.25 62.18,14.29 64.1,16.22 74.18,16.22
GND on ART03 (solid shape): 123.09,43.13 123.09,42.06 123.7,41.45 123.7,40.84 123.09,40.23 123.09,28.93 122.83,28.68 119.96,28.68 119.71,28.93 119.71,30.08 119.9,30.27 119.96,30.36 119.98,30.47 119.98,31.37 119.96,31.48 119.9,31.58 119.71,31.77 119.71,32.36 119.9,32.68 119.71,33 119.71,33.29 119.9,33.61 119.71,33.92 119.71,34.55 119.87,34.71 119.94,34.81 119.96,34.92 119.96,35.82 119.94,35.93 119.87,36.02 119.71,36.19 119.71,37.44 119.92,37.65 119.98,37.74 120,37.85 120,38.65 119.98,38.77 119.92,38.86 119.71,39.06 119.71,40.51 120.02,40.82 120.02,41.93 119.71,42.24 119.71,43.13 119.91,43.33 122.89,43.33
GND on ART03 (solid shape): outline of 111 points within 104.71,16.43 111.28,19.35
GND on ART03 (solid shape): outline of 107 points within 90.45,69.33 94.31,72.1
GND on ART03 (solid shape): outline of 152 points within 108.52,32.63 114.23,37.28
GND on ART03 (solid shape): outline of 172 points within 7.51,73.45 14.53,77.55
GND on ART03 (solid shape): 87.77,65.83 87.66,65.7 87.62,65.53 87.73,65.26 88,65.15 88.93,65.15 89.2,65.26 89.31,65.53 89.27,65.7 89.16,65.83 89.53,65.83 90.02,65.35 90.02,64.78 90,64.76 89.75,64.64 89.65,64.38 89.76,64.11 90.03,64 90.96,64 91.23,64.11 91.34,64.38 91.24,64.63 90.99,64.76 90.98,64.76 90.98,65.35 91.46,65.83 91.84,65.83 91.73,65.7 91.7,65.53 91.81,65.26 92.08,65.15 93,65.15 93.27,65.26 93.38,65.53 93.34,65.7 93.23,65.83 93.7,65.83 93.82,65.62 94.06,65.53 94.09,65.53 94.13,65.54 94.46,65.21 94.46,62.27 93.27,61.08 85.34,61.08 84.81,61.61 84.81,65.06 85.9,65.06 85.96,65 85.96,64.71 85.94,64.69 85.69,64.57 85.59,64.31 85.7,64.04 85.97,63.93 86.89,63.93 87.16,64.04 87.27,64.31 87.17,64.57 86.92,64.69 86.92,64.7 86.92,65.4 86.65,65.66 86.63,65.77 86.73,65.83
GND on ART03 (solid shape): outline of 228 points within 83.59,15.24 93.88,18.67
GND on ART03 (solid shape): outline of 245 points within 85.57,83.35 92.84,88.66
GND on ART04 (solid shape): 84.51,119.24 84.51,117.27 84.25,117.02 74.67,117.02 74.41,117.27 74.41,117.96 75.66,117.96 75.66,117.91 75.67,117.86 75.69,117.81 75.72,117.76 75.75,117.72 75.79,117.69 75.84,117.66 75.88,117.63 75.94,117.62 75.99,117.61 76.04,117.61 76.09,117.62 76.13,117.63 76.18,117.65 76.2,117.66 82.6,117.66 83.21,118.27 83.25,118.28 83.29,118.3 83.34,118.33 83.38,118.36 83.41,118.4 83.44,118.44 83.46,118.49 83.47,118.54 83.48,118.59 83.48,118.64 83.47,118.7 83.45,118.75 83.43,118.8 83.4,118.85 83.36,118.89 83.31,118.92 83.26,118.95 83.21,118.96 83.15,118.97 83.1,118.97 83.05,118.97 83,118.95 82.95,118.93 82.91,118.9 82.87,118.87 82.84,118.83 82.81,118.79 82.79,118.74 82.78,118.7 82.35,118.27 76.2,118.27 76.18,118.28 76.13,118.3 76.09,118.31 76.04,118.32 75.99,118.32 75.94,118.31 75.88,118.3 75.84,118.27 75.79,118.24 75.75,118.21 75.72,118.17 75.69,118.12 75.67,118.07 75.66,118.02 75.66,117.96 74.41,117.96 74.41,119.24 74.67,119.49 84.25,119.49
GND on ART04 (solid shape): 85.88,114.48 85.88,112.52 84.99,111.63 80.87,111.63 79.98,112.52 79.98,114.02 80.52,114.02 80.52,114 80.53,113.94 80.54,113.89 80.56,113.85 80.59,113.8 80.63,113.76 80.67,113.73 80.71,113.7 80.76,113.68 80.79,113.68 81.82,112.64 84.77,112.64 84.79,112.63 84.83,112.61 84.88,112.6 84.93,112.59 84.98,112.59 85.03,112.6 85.08,112.62 85.13,112.64 85.17,112.67 85.21,112.7 85.24,112.75 85.27,112.79 85.29,112.84 85.3,112.89 85.31,112.95 85.3,113 85.29,113.05 85.27,113.1 85.24,113.15 85.21,113.19 85.17,113.23 85.13,113.26 85.08,113.28 85.03,113.3 84.98,113.3 84.93,113.3 84.88,113.3 84.83,113.28 84.79,113.26 84.77,113.25 82.07,113.25 81.22,114.11 81.21,114.13 81.19,114.18 81.17,114.23 81.13,114.27 81.09,114.3 81.05,114.33 81,114.35 80.95,114.37 80.9,114.38 80.85,114.38 80.79,114.37 80.74,114.35 80.69,114.33 80.64,114.29 80.6,114.25 80.57,114.21 80.54,114.16 80.53,114.11 80.52,114.05 80.52,114.02 79.98,114.02 79.98,114.76 80.11,114.88 85.47,114.88
GND on ART04 (solid shape): outline of 490 points within 75.82,71.83 92.51,81.79
GND on TOP: 17.65,57.91 18.52,57.91 19.17,58.55 21.8,58.55 22.12,58.88 22.12,59.59 21.89,59.82 17.65,59.82 17.53,59.69 17.53,58.04 ; 2 cut-outs
GND on TOP: 108.89,71.6 108.56,71.27 107.9,71.27 107.72,71.45 107.72,75.56 107.42,75.87 103.53,75.87 102.81,76.59 101.51,76.59 101.27,76.83 101.27,77.47 101.37,77.57 106.22,77.57 106.63,77.98 108.2,77.98 108.89,77.29 ; 4 cut-outs
GND on TOP: 96.62,93.09 98.12,93.09 98.37,92.84 98.37,90.81 98.09,90.53 96.57,90.53 96.34,90.75 96.34,92.81
GND on TOP: 59.16,44.6 64.36,44.6 64.52,44.45 64.52,44.12 64.72,43.92 66.12,43.92 66.29,43.74 66.29,43.48 65.88,43.48 65.88,43 61.92,43 61.68,43.24 59.95,43.24 59.71,43.49 58.99,43.49 58.93,43.56 58.93,44.37 ; 6 cut-outs
GND on TOP: 97.56,73.51 100.36,73.51 100.48,73.38 100.48,71.83 100.08,71.42 97.66,71.42 97.46,71.63 97.46,73.41 ; 3 cut-outs
GND on TOP: 49.2,44.22 53.95,44.22 54.03,44.15 54.03,43.94 53.75,43.94 53.75,43.89 51.94,43.89 51.59,43.54 51.36,43.54 50.22,42.39 49.58,42.39 49.45,42.52 49.45,43.23 49.12,43.56 49.12,44.15 ; 4 cut-outs
GND on TOP: 83.19,106.83 83.19,106.2 83.11,106.13 83.11,103.48 83.08,103.45 82.43,103.45 82.07,103.81 82.07,105.99 81.74,106.32 81.74,106.86 81.86,106.98 83.03,106.98 ; 3 cut-outs
GND on TOP: 80.9,87.25 86.89,87.25 88.39,88.75 88.39,91.69 88.29,91.8 84.12,91.8 84.05,91.72 84.05,91.36 83.87,91.19 81.28,91.19 80.9,90.81 ; 7 cut-outs
GND on TOP: 105.36,82.19 102.69,82.19 102.41,81.92 102.41,81.08 103.12,80.37 105.64,80.37 105.94,80.67 105.94,81.61
GND on TOP: 95.78,90.7 95.78,91.29 95.66,91.41 93.32,91.41 93.12,91.21 93.12,90.7 93.29,90.53 95.61,90.53 ; 2 cut-outs
GND on TOP: 65.28,97.92 71.37,97.92 72.26,97.03 72.26,89.03 71.63,88.39 65.02,88.39 64.26,89.15 64.26,96.9 ; 4 cut-outs
GND on TOP: 96.14,87 97.84,87 97.92,87.07 97.92,89.76 97.76,89.92 96.9,89.92 96.65,89.66 96.65,88.01 96.01,87.38 96.01,87.12 ; 2 cut-outs
GND on ART02, ART05: 0.51,117 1.24,118.76 3,119.49 132,119.49 133.76,118.76 134.49,117 134.49,3 133.76,1.24 132,0.51 111.38,0.51 111.38,3.26 111.63,4.16 110.87,4.7 100.83,4.7 100.07,4.16 100.32,3.26 100.32,0.51 48.53,0.51 48.53,3.63 49,4.76 48.03,5.51 47.21,5.51 47.21,11.78 47.67,12.91 46.7,13.66 33.2,13.66 32.23,12.91 32.69,11.78 32.69,5.51 31.87,5.51 30.9,4.76 31.37,3.63 31.37,0.51 3,0.51 1.24,1.24 0.51,3 0.51,31.82 31.54,31.82 33.32,30.04 33.32,20.93 33.96,20.29 34.59,20.93 34.59,30.3 34.55,30.55 34.41,30.75 32.26,32.9 32.05,33.04 31.81,33.09 0.51,33.09 ; 1 cut-out
GND on ART03: 63.83,93.09 63.83,88.67 66.78,85.72 69.9,85.72 73.18,82.45 73.18,82.09 74.68,80.59 78.38,80.59 78.97,81.18 78.97,84.48 72.36,91.08 69.14,91.08 66.62,93.6 64.34,93.6
VBUS_USB_TYPEC on TOP (solid shape): 101.27,10.74 101.27,10.64 101.37,10.54 102.5,10.54 102.5,10.28 102.37,10.16 102.37,9.93 101.24,9.93 101,9.68 100.3,9.68 100.25,9.73 100.25,9.91 100.81,9.91 100.81,10.41 100.43,10.41 100.43,9.91 100.25,9.91 100.25,10.67 100.48,10.9 101.12,10.9
VBUS_USB_TYPEC on BOTTOM (solid shape): 101.98,10.79 101.98,8.91 101.95,8.9 101.71,8.56 101.95,8.23 101.98,8.21 101.98,8.15 102.18,7.95 102.16,7.92 102.11,7.82 102.1,7.72 102.2,7.47 102.46,7.36 102.56,7.38 102.65,7.42 102.69,7.44 103.4,6.73 107.52,6.73 108.13,6.12 108.13,5.41 108.09,5.33 108.01,5.31 107.95,5.32 107.9,5.32 107.03,5.32 106.78,5.56 106.8,5.64 106.8,5.71 106.66,6.07 106.3,6.22 106.09,6.18 105.92,6.06 105.85,6.02 105.77,6.05 105.6,6.17 105.4,6.22 105.04,6.07 104.89,5.71 104.9,5.62 104.92,5.53 104.58,5.19 104.13,5.19 103.98,5.29 103.8,5.32 103.72,5.31 103.64,5.29 103.45,5.29 102.93,5.82 102.92,5.87 102.72,6.28 102.3,6.45 101.96,6.45 101.96,6.65 101.74,7.2 101.18,7.43 101.18,7.43 100.56,8.05 100.56,10.64 100.97,11.05 101.73,11.05
(no net) on TOP: 91.59,102.84 91.59,102.31 91.54,102.26 91.41,102.26 91.39,102.29 91.39,103.28 92.43,104.32 92.43,104.42 92.71,104.7 92.71,105.66 92.8,105.76 93.82,105.76 93.89,105.68 93.89,105.14
(no net) on TOP: 100.46,98.61 100.43,98.58 100.43,95.98 100.33,95.89 100.33,95.25 98.93,95.25 98.81,95.38 98.81,97.28 98.73,97.36 98.73,100.31 98.6,100.44 98.6,101.96 98.73,102.08 98.73,105.84 102.11,109.22 105.28,109.22 106.55,107.95 106.55,106.43 103.38,103.25 101.22,103.25 100.46,102.49 100.46,98.62 ; 4 cut-outs
(no net) on TOP: 98.37,105.87 98.37,103.38 98.45,103.3 98.45,102.26 98.32,102.13 97.66,102.13 97.51,102.29 97.51,102.74 96.98,103.28 96.98,104.57 96.49,105.05 95.28,105.05 95.27,105.06 94.63,105.06 94.35,105.34 94.35,105.73 94.11,105.97 92.78,105.97 92.68,106.07 92.68,106.88 92.72,106.91 93.88,106.91 94.53,106.25 95.55,106.25 95.55,106.25 97.99,106.25 ; 4 cut-outs
(no net) on TOP: 81.28,104.52 82.54,103.26 83.38,103.26 84.2,102.44 84.2,101.73 83.31,101.73 82.8,102.23 81.79,102.23 81.06,102.96 74.64,102.96 74.04,102.36 74.04,99.97 73.81,99.75 72.11,99.75 71.7,100.15 71.7,103.91 72.31,104.52
(no net) on TOP: 79.38,101.09 80.67,101.09 80.67,98.6 80.87,98.4 81.64,98.4 81.81,98.22 81.81,96.29 81.53,96.01 81.53,92.32 80.77,88.65 80.64,88.52 80.64,87.38 80.14,86.87 79.38,86.87 78.87,87.38 78.87,92.08 78.99,92.2 78.97,92.23 78.97,100.69 ; 2 cut-outs
(no net) on TOP: 84.79,103.07 84.79,102.26 84.58,102.26 84.53,102.31 84.53,102.72 83.97,102.72 83.58,103.11 83.58,103.29 83.41,103.46 83.41,106.63 83.79,107.01 84.68,107.01 84.86,106.83 84.86,106.48 84.35,105.97 84.35,103.5 ; 3 cut-outs
(no net) on TOP: 97.02,100.06 96.47,100.61 96.47,101.3 95.53,102.23 91.82,102.23 91.8,102.26 91.8,102.87 93.19,104.27 93.75,104.27 93.99,104.03 96.51,104.03 96.75,103.78 96.75,103.35 97.5,102.6 97.5,102.02 97.71,101.8 98.22,101.8 98.35,101.68 98.35,100.33 98.56,100.11 98.56,97.92 98.55,97.9 98.55,93.6 98.42,93.47 97.28,93.47 97.02,93.74 ; 3 cut-outs
HDMI0_TX_5V on BOTTOM (solid shape): outline of 451 points within 58.37,12.27 65.68,23.57
HUB_1V2_LX on TOP (solid shape): 79.07,104.52 79.21,104.42 79.38,104.38 79.68,104.38 79.68,104.34 80.54,104.34 80.54,104.37 81.33,104.37 81.33,104.38 81.39,104.41 82.45,103.35 82.45,103.3 82.5,103.3 82.54,103.26 83.38,103.26 84.2,102.44 84.2,101.73 83.31,101.73 82.8,102.23 81.94,102.23 81.94,102.92 81.13,102.92 81.11,102.91 81.06,102.96 74.64,102.96 74.04,102.36 74.04,99.97 73.81,99.75 72.11,99.75 71.7,100.15 71.7,103.91 72.31,104.52
HUB_1V2_SWR on TOP: 108.41,83.67 108.41,82.17 108.76,81.81 111.2,81.81 111.56,82.17 111.56,83.62 111.28,83.9 108.64,83.9
HUB_3V3_LX on TOP (solid shape): 93.89,105.68 93.89,105.14 93.14,104.39 93.14,104.39 91.75,103.01 91.64,103.01 91.64,102.89 91.59,102.84 91.59,102.31 91.54,102.26 91.41,102.26 91.39,102.29 91.39,103.28 92.2,104.09 92.33,104.09 92.33,104.22 92.43,104.32 92.43,104.42 92.71,104.7 92.71,105.66 92.8,105.76 93.82,105.76
USB0_5V0 on TOP (solid shape): 52.17,11.66 52.17,1.42 51.92,1.17 50.22,1.17 49.84,1.54 49.84,11.76 49.99,11.91 51.92,11.91
USB0_5V0 on TOP (solid shape): 46.2,29.84 46.2,29.29 46.53,28.96 46.79,28.96 46.79,28.7 47.07,28.7 47.07,28.5 47.02,28.45 45.16,28.45 45.03,28.57 46.2,28.57 46.2,28.83 45.82,28.83 45.82,28.57 45.03,28.57 44.86,28.75 44.86,29.21 45.95,29.21 45.95,29.62 45.62,29.62 45.62,29.21 44.86,29.21 44.86,29.77 45.01,29.92 45.44,29.92 45.44,29.91 46.1,29.91 46.1,29.95
USB0_5V0 on BOTTOM (solid shape): outline of 894 points within 33.83,6.52 53.42,29.69
USB1_5V0 on TOP (solid shape): 56.26,18.54 56.26,15.7 56.57,15.39 56.57,15.36 57.23,15.36 57.23,15.39 57.33,15.29 57.33,14.73 57.66,14.4 57.91,14.4 57.91,14.15 58.19,14.15 58.19,13.94 58.14,13.89 56.18,13.89 56.06,14.02 57.33,14.02 57.33,14.27 56.95,14.27 56.95,14.02 56.06,14.02 55.5,14.58 55.5,14.66 57.07,14.66 57.07,15.06 56.74,15.06 56.74,14.66 55.5,14.66 55.5,15.19 55.07,15.62 48.87,15.62 48.62,15.88 48.62,19.18 48.87,19.43 55.37,19.43
USB1_5V0 on ART03 (solid shape): outline of 693 points within 35.33,12.67 50.56,17.75
USB_VBUS_CON on TOP (solid shape): 99.45,14.12 99.45,13.28 98.82,12.65 98.82,12.31 98.2,11.68 98.2,10.92 97.41,10.13 97.41,7.87 97.66,7.62 99.34,7.62 100.28,8.56 100.28,8.64 100.81,8.64 100.81,9.12 100.43,9.12 100.43,8.64 100.28,8.64 100.28,9.27 100.36,9.35 100.89,9.35 101.02,9.22 101.02,7.9 99.34,6.22 96.44,6.22 96.27,6.4 97.84,6.4 97.84,6.63 97.49,6.63 97.49,6.4 96.27,6.4 96.01,6.65 96.01,7.21 97.89,7.21 97.89,7.47 97.49,7.47 97.49,7.21 96.01,7.21 96.01,11.3 96.91,12.2 97.65,12.2 98.32,12.88 98.32,13.41 99.24,13.41 99.24,13.68 98.86,13.68 98.86,13.41 98.32,13.41 98.32,14.05 98.5,14.22 99.35,14.22
USB_VBUS_CON on ART03 (solid shape): outline of 191 points within 95.68,11.4 103.15,23.34
V_3V3_USBHUB0 on TOP (solid shape): 96.39,90.2 96.39,89.61 95.91,89.13 95.91,88.49 95.3,87.88 95.29,87.88 95.03,87.63 95.03,86.89 94.58,86.44 94.12,86.44 93.89,86.21 93.89,85.55 93.45,85.11 93.45,84.34 93.41,84.3 93.25,84.3 93.25,84.98 93.05,84.98 93.05,84.3 92.85,84.3 92.85,84.98 92.65,84.98 92.65,84.3 92.49,84.3 92.45,84.35 92.45,85.12 93.08,85.75 93.08,85.88 93.74,85.88 93.74,86.26 93.48,86.26 93.48,85.88 93.08,85.88 93.08,86.79 93.43,87.15 93.43,88.87 94.91,90.35 96.24,90.35
V_3V3_USBHUB0 on ART04 (solid shape): outline of 120 points within 95.48,89.38 104.09,93.84
V_3V3_USBHUB0 on TOP: 99.48,77.52 100.69,77.52 101.12,77.09 101.12,76.81 101.52,76.4 102.62,76.4 103.38,75.64 107.01,75.64 107.34,75.31 107.34,73.18 107.16,73 102.27,73 100.27,75.01 100.27,77.19 100.14,77.32 99.48,77.32 99.43,77.37 99.43,77.47 ; 1 cut-out
V_3V3_USBHUB0 on BOTTOM: 104.09,74.85 104.09,74.04 104.39,73.74 106.68,73.74 107.8,74.85 107.8,77.88 107.34,78.33 107.34,91.08 104.5,93.93 103.56,93.93 103.28,93.65 103.28,92.08 105.51,89.84 105.51,86.72 104.62,85.83 104.62,75.39
V_5V0_HUB on TOP (solid shape): 84.86,106.83 84.86,106.48 84.35,105.97 84.35,104.49 84.33,104.47 84.3,104.43 84.27,104.39 84.25,104.34 84.23,104.29 84.23,104.24 84.23,104.19 84.23,104.13 84.25,104.08 84.28,104.03 84.31,103.99 84.33,103.97 84.33,103.63 84.33,103.61 84.34,103.55 84.35,103.5 84.79,103.07 84.79,102.26 84.58,102.26 84.53,102.31 84.53,102.72 84.1,102.72 83.58,103.24 83.58,103.29 83.41,103.46 83.41,103.56 84.12,103.56 84.12,103.86 83.64,103.86 83.64,103.56 83.41,103.56 83.41,104.47 84.1,104.47 84.1,104.78 83.64,104.78 83.64,104.47 83.41,104.47 83.41,105.38 84.1,105.38 84.1,105.69 83.67,105.69 83.67,105.38 83.41,105.38 83.41,106.63 83.79,107.01 84.68,107.01
V_5V0_HUB on TOP (solid shape): outline of 109 points within 91.8,93.47 98.56,104.27
V_5V0_HUB on ART04: 86.18,104.17 88.06,102.29 91.14,102.29 93.37,104.52 93.98,104.52 94.28,104.22 94.28,103.78 94.25,103.75 94.25,102.81 92.05,100.61 85.45,100.61 83.54,102.51 83.54,106.73 83.77,106.96 85.12,106.96 86.18,105.89
V_12V0_CON_IN on TOP (solid shape): 115.37,14.17 115.37,13.51 116.33,12.55 121.13,12.55 121.39,12.29 121.39,9.93 120.6,9.14 114.12,9.14 113.06,10.21 113.06,14.27 113.13,14.35 115.19,14.35
V_12V0_CON_IN_F on TOP (solid shape): 115.06,22.28 115.06,17.12 115.47,16.71 117.91,16.71 118.11,16.51 118.11,15.01 118.01,14.91 116.13,14.91 115.35,15.68 112.81,15.68 112.25,16.25 112.25,19.34 111.93,19.66 110.32,19.66 109.79,20.19 109.79,22.73 110.18,23.11 114.23,23.11
V_12V0_SENSE on TOP (solid shape): 109.22,27.58 109.22,24.94 109.55,24.61 110.87,24.61 111.02,24.46 111.02,23.7 110.92,23.6 107.98,23.6 107.49,23.11 107.36,23.11 107.36,19.99 107.08,19.71 104.34,19.71 104.14,19.91 104.14,21.5 103.17,22.46 103.17,27.94 103.48,28.24 108.56,28.24
V_12V0_SENSE on BOTTOM (solid shape): 108.94,28.02 108.94,23.65 108.81,23.52 103.23,23.52 103.1,23.65 103.1,28.02 103.23,28.14 108.81,28.14
V_AVDD_1V0_PHY0 on TOP (solid shape): 8.36,68.73 8.36,67.72 8.33,67.69 6.55,67.69 6.38,67.87 8.07,67.87 8.07,68.25 7.59,68.25 7.59,67.87 6.38,67.87 6.3,67.94 6.3,68.61 6.48,68.78 8.31,68.78
V_AVDD_1V0_PHY0 on BOTTOM (solid shape): outline of 586 points within 5.36,49.15 13.56,69.52
V_AVDD_1V0_PHY1 on TOP (solid shape): 52.68,28.27 52.68,27.69 52.55,27.56 51.49,27.56 51.34,27.7 51.34,27.76 52.04,27.76 52.04,28.12 51.64,28.12 51.64,27.76 51.34,27.76 51.34,28.25 51.46,28.37 52.58,28.37
V_AVDD_1V0_PHY1 on ART03 (solid shape): 56.23,30.63 59.36,30.63 59.36,29.21 58.4,28.25 55.9,28.25 55.81,28.31 55.82,28.41 55.88,28.52 55.9,28.64 55.54,28.99 55.18,28.64 55.2,28.52 55.26,28.41 55.27,28.31 55.18,28.25 54.39,28.25 53.9,27.76 53.79,27.73 53.73,27.82 53.62,28.06 53.37,28.16 53.12,28.06 53.02,27.81 53.05,27.66 53.13,27.54 53.16,27.43 53.06,27.37 52.01,27.37 51.69,27.69 51.69,28.19 52.35,28.86 52.4,28.85 52.59,28.91 52.72,29.06 52.73,29.07 53.82,30.17 53.82,30.33 53.9,30.4 53.9,31.06 54.51,31.67 55.18,31.67
V_AVDD_3V3_PHY0 on TOP (solid shape): 7.82,49.68 7.82,49.56 7.42,49.56 7.42,49.28 7.82,49.28 7.82,48.69 7.39,48.69 7.39,48.34 7.6,48.34 7.69,48.27 7.67,48.16 7.64,48.13 7.11,48.13 7.11,48.82 7.05,48.82 7.05,49.73 7.18,49.86 7.64,49.86
V_DV11_HUB on TOP (solid shape): 97.05,99.52 97.05,98.65 96.9,98.5 93.81,98.5 93.75,98.45 93.75,97.79 93.63,97.67 92.37,97.67 92.35,97.69 92.35,97.84 92.38,97.87 93.07,97.87 93.09,97.89 93.15,97.89 93.15,98.7 96.22,98.7 96.22,99.21 95.94,99.21 95.94,98.7 95.33,98.7 95.33,99.21 95.02,99.21 95.02,98.7 93.15,98.7 93.15,98.73 94.41,98.73 94.41,99.21 94.11,99.21 94.11,98.73 93.15,98.73 93.15,98.85 93.07,98.85 93.03,98.88 92.3,98.88 92.28,98.91 92.28,99.03 92.3,99.06 93.04,99.06 93.07,99.09 93.15,99.09 93.15,99.17 93.62,99.64 96.93,99.64
V_DV11_HUB on TOP (solid shape): outline of 82 points within 91.68,91.69 96.34,95.45
V_DV11_HUB on TOP: 82.8,101.35 82.68,101.22 78.74,101.22 78.23,100.71 78.23,87.38 77.98,87.12 76.96,87.12 76.71,87.38 76.71,97.92 74.78,99.85 74.78,102.18 74.9,102.31 78.23,102.31 78.56,101.98 82.73,101.98 82.8,101.9 ; 3 cut-outs
V_DV11_HUB on ART04: 76.3,99.72 76.71,100.13 90.07,100.13 90.6,99.59 96.6,99.59 96.93,99.26 96.93,98.32 96.32,97.71 90.88,97.71 90.12,96.95 90.12,94.79 87.71,92.38 81.43,92.38 77.72,88.67 76.71,88.67 76.3,89.08
V_DV12_HUB on TOP (solid shape): 99.71,75.9 99.71,75.5 100.41,74.8 100.41,73.96 100.28,73.84 97.26,73.84 97,74.09 100.23,74.09 100.23,74.47 99.97,74.47 99.97,74.09 97,74.09 96.98,74.12 99.21,74.12 99.21,74.55 98.91,74.55 98.91,74.12 98.17,74.12 98.17,74.52 97.89,74.52 97.89,74.12 96.98,74.12 96.45,74.65 96.45,76.09 96.48,76.12 96.63,76.12 96.65,76.11 96.65,75.45 96.86,75.23 97.4,75.23 97.39,75.12 97.4,75.07 97.42,75.02 97.44,74.97 97.47,74.93 97.51,74.89 97.55,74.86 97.59,74.83 97.64,74.81 97.7,74.8 97.75,74.79 97.8,74.8 97.85,74.81 97.9,74.83 97.95,74.86 97.99,74.89 98.03,74.93 98.06,74.97 98.08,75.02 98.1,75.07 98.11,75.12 98.1,75.23 98.77,75.23 98.85,75.32 98.85,76.1 98.92,76.17 99.43,76.17
V_DV12_HUB on TOP (solid shape): outline of 89 points within 99.45,77.75 111.38,81.12
V_DV12_HUB on BOTTOM: 98.12,74.02 99.69,74.02 101.02,75.34 101.02,76.78 102.54,78.31 102.54,82.35 97.56,87.33 96.77,87.33 96.39,86.94 96.39,85.72 98.81,83.31 98.81,77.24 97.92,76.35 97.92,74.22
V_DV12_HUB on ART03: 90.91,76 90.91,75.18 91.44,74.65 94.44,74.65 94.51,74.73 94.51,75.31 93.01,76.81 93.01,78.11 92.43,78.69 91.49,78.69 90.96,78.16 90.96,76.05
V_DV12_HUB on ART04: 95.5,75.84 99.77,75.84 100.41,75.21 100.41,73.74 99.97,73.3 97.36,73.3 96.85,73.81 93.27,73.81 92.75,74.33 92.75,77.38 92.05,78.08 91.62,78.08 91.41,78.28 91.41,78.51 91.59,78.69 92.66,78.69
V_DV33_HUB on TOP (solid shape): 94.53,106.25 95.55,106.25 95.55,106.25 97.99,106.25 98.37,105.87 98.37,103.38 98.45,103.3 98.45,102.26 98.32,102.13 97.66,102.13 97.63,102.17 97.63,102.57 98.22,102.57 98.22,102.97 97.97,102.97 97.97,102.57 97.63,102.57 97.63,102.66 96.98,103.3 96.98,103.38 98.09,103.38 98.09,103.66 97.69,103.66 97.69,103.38 96.98,103.38 96.98,104.42 98.07,104.42 98.07,104.67 97.64,104.67 97.64,104.42 96.98,104.42 96.98,104.57 96.49,105.05 95.28,105.05 95.27,105.06 94.63,105.06 94.35,105.34 94.35,105.73 94.18,105.89 94.18,105.92 94.16,105.92 94.11,105.97 93.19,105.97 93.19,106.08 92.68,106.08 92.68,106.3 93.8,106.3 93.8,106.69 93.42,106.69 93.42,106.3 92.68,106.3 92.68,106.88 92.72,106.91 93.88,106.91
V_DV33_HUB on ART03: 84.07,92.51 90.04,92.51 91.14,93.6 91.14,94.64 90.96,94.82 89.38,94.82 88.75,94.18 84.07,94.18 83.95,94.06 83.95,92.63
